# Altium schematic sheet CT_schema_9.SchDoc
size 147 x 119 mm
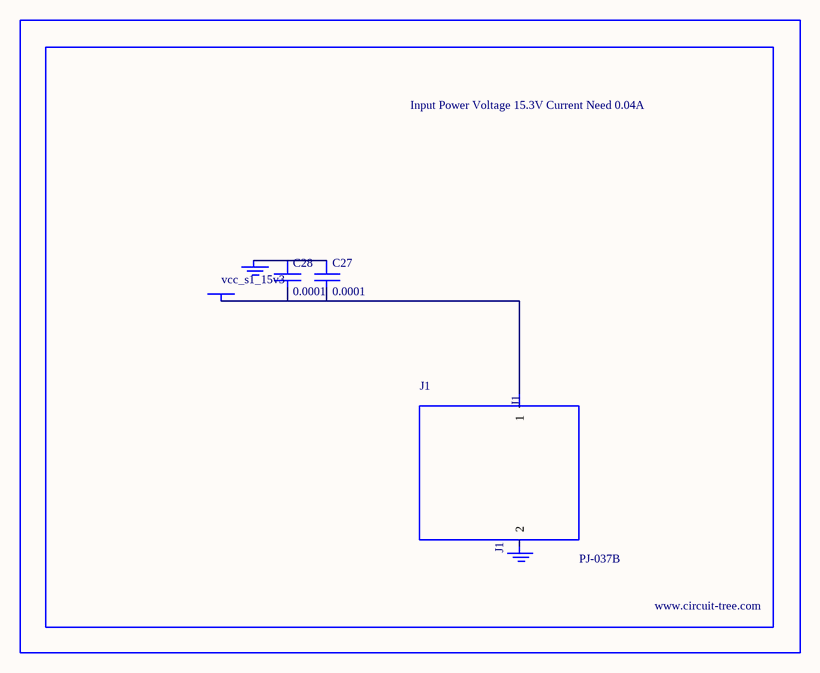
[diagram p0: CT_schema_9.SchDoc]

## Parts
BORDER8  (no value)
C27  0.0001  [EXV-9H]
C28  0.0001  [EXV-9H]
GND_INSTANCE_8_0  (no value)
GND_INSTANCE_8_1  (no value)
J1  PJ-037B  [PJ-037B_PACKAGE]
POWER_INSTANCE_8_0  vcc_s1_15v3

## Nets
NetC27_1: C27.1 C28.1 GND_INSTANCE_8_0.0(GND)
NetC27_2: C27.2 C28.2 J1.1 POWER_INSTANCE_8_0.0(PWR)

Not connected (* = marked no-connect by the designer): GND_INSTANCE_8_1 0(GND); J1 2

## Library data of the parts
BORDER8 = BORDER_PAGE8
C27 C28 = EDK107M035A9HAA
GND_INSTANCE_8_0 GND_INSTANCE_8_1 = GND
POWER_INSTANCE_8_0 = PWR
